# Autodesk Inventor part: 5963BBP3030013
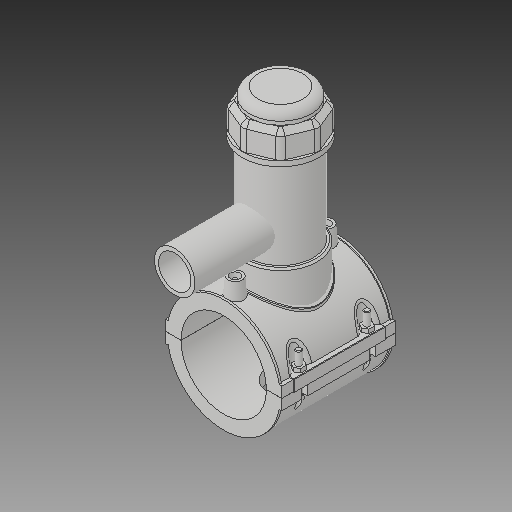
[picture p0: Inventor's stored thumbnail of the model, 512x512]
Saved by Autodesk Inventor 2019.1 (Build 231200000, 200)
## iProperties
Created: 2017-07
Part Number: 5963BBP3030013
Material: Generic
Description: PLASSON TAPPING SADDLE 3''IPS x 1 1/4''IPS
Document SubType Name: Modeling
Designer: KIM
Density: 1 g/cm^3
Appearance: Default
Author: KIM
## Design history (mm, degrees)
derived "5963BBP_5963BUP.ipt"
feature "Solid1::5963BBP_5963BUP.ipt"
feature "Solid2::5963BBP_5963BUP.ipt"
feature "Solid3::5963BBP_5963BUP.ipt"
tag "TaggingFeature1"
body "Solid1"
body "Solid2"
body "Solid3"
other parameters: "d_" = 88.7, "B_" = 120.904, "L_" = 118.11, "d_t" = 6, "H_2" = 177.038, "H_1" = 65.024, "d_1" = 42.1, "H_" = 109.982, "d1" = 115.31, "d148" = 1.3305, "d160" = 1.3305, "d169" = 3.2805, "d192" = 6.9984, "d0" = 88.7, "d2" = 120.904, "d3" = 22.175, "d4" = 118.11, "d5" = 0, "d6" = 0.1, "d8" = 0, "d19" = 6, "d20" = 6, "d21" = 70.866, "d23" = 0, "d24" = 35.433, "d26" = 0, "d27" = 3, "d28" = 3, "d29" = 3, "d30" = 29.56667, "d31" = 6, "d32" = 0, "d33" = 0, "d34" = 0.6, "d40" = 59.9612, "d41" = 79.83, "d43" = 0, "d45" = 0, "d47" = 128.521, "d70" = 15, "d72" = 0, "d73" = 6, "d75" = 5, "d76" = 0, "d77" = 4.435, "d78" = 74.35, "d79" = 15, "d80" = 47.244, "d82" = 5 deg, "d84" = 4, "d85" = 14, "d86" = 0, "d87" = 3, "d88" = 0, "d89" = 1, "d90" = 1, "d91" = 94.488, "d92" = 0, "d93" = 0.5, "d94" = 46.68421, "d96" = 117.6162, "d97" = 2.3622, "d98" = 0, "d102" = 0.887, "d120" = 140 deg, "d121" = 24.228, "d122" = 20 deg, "d123" = 230.62, "d124" = 69.186, "d126" = 0, "d143" = 91.361, "d145" = 20.46923, "d149" = 1.3305, "d150" = 22.51615, "d153" = 118.11, "d154" = 0, "d156" = 57.655, "d157" = 160 deg, "d159" = 5.322, "d161" = 1.3305, "d162" = 70.866, "d163" = 0, "d164" = 44.35, "d167" = 8.87, "d168" = 56.24878, "d170" = 3.2805, "d172" = 0, "d173" = 1, "d175" = 44.35, "d176" = 20 deg, "d177" = 6.209, "d178" = 26.61, "d180" = 0, "d183" = 10.644, "d184" = 4.9672, "d185" = 38.38575, "d186" = 38.38575, "d187" = 57.655, "d188" = 7.983, "d189" = 6.209, "d190" = 0, "d191" = 86.4825, "d193" = 6.9984, "d194" = 4.13385, "d195" = 90 deg, "d197" = 0, "d199" = 0, "d200" = 13.305, "d202" = 0, "d203" = 177.038, "d204" = 75.8385, "d205" = 55.881, "d206" = 67.8555, "d207" = 132.7785, "d208" = 138.08964, "d209" = 164.64534, "d210" = 68.6538, "d211" = 79.83, "d212" = 63.864, "d213" = 39.5766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
